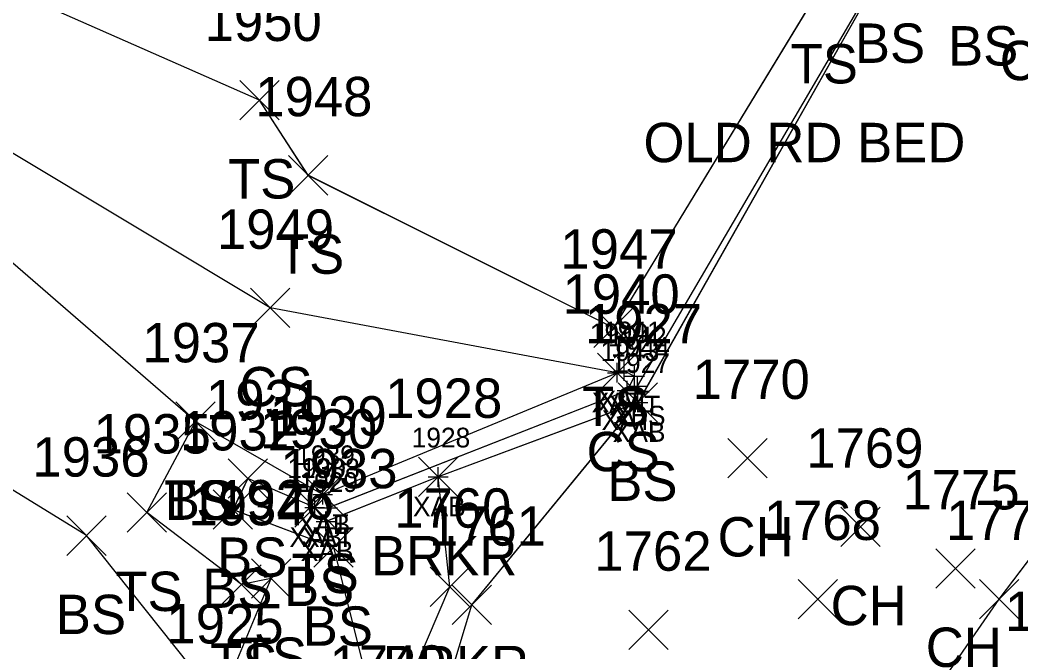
# Model space of a CAD drawing. Extents: x 1415642 to 1422021, y 544543 to 547232.
# Drawn here: x 1416156.1 to 1416207, y 546868.3 to 546900.4 of the extents above; entities that cross this region are included whole.
import ezdxf

# ---------------------------------------------------------------- set-up
doc = ezdxf.new("R2010")
doc.units = 0
for name, color, linetype in [('B_A', 7, 'Continuous'), ('B_I', 7, 'Continuous'), ('B_TIC', 7, 'Continuous'), ('BSE', 7, 'Continuous'), ('BSUBM', 7, 'Continuous'), ('L_A', 7, 'Continuous'), ('L_C', 7, 'Continuous'), ('L_I', 7, 'Continuous'), ('L_TIC', 7, 'Continuous'), ('LAWE', 7, 'Continuous'), ('LELB', 7, 'Continuous')]:
    doc.layers.add(name, color=color, linetype=linetype)

msp = doc.modelspace()

# ---------------------------------------------------------------- linework, layer by layer
at = {"layer": 'B_TIC'}
for p, q in [((1416186.471, 546882.455), (1416186.546, 546882.455)), ((1416186.817, 546882.554), (1416186.892, 546882.554)), ((1416187.348, 546882.292), (1416187.423, 546882.292)), ((1416186.972, 546881.556), (1416187.048, 546881.556)), ((1416186.972, 546881.556), (1416187.048, 546881.556)), ((1416187.506, 546881.78), (1416187.581, 546881.78)), ((1416187.522, 546880.949), (1416187.598, 546880.949)), ((1416177.376, 546877.166), (1416177.451, 546877.166)), ((1416171.517, 546876.268), (1416171.592, 546876.268)), ((1416171.517, 546876.268), (1416171.592, 546876.268)), ((1416171.104, 546875.611), (1416171.18, 546875.611)), ((1416171.763, 546875.605), (1416171.839, 546875.605)), ((1416171.763, 546875.605), (1416171.839, 546875.605)), ((1416171.677, 546874.904), (1416171.752, 546874.904))]:
    msp.add_line(p, q, dxfattribs=at)
for points in [[(1416186.467, 546881.955), (1416186.467, 546882.955)], [(1416186.813, 546882.054), (1416186.813, 546883.054)], [(1416185.967, 546882.455), (1416186.967, 546882.455)], [(1416186.313, 546882.554), (1416187.313, 546882.554)], [(1416187.344, 546881.792), (1416187.344, 546882.792)], [(1416186.844, 546882.292), (1416187.844, 546882.292)], [(1416186.969, 546881.056), (1416186.969, 546882.056)], [(1416186.969, 546881.056), (1416186.969, 546882.056)], [(1416187.502, 546881.28), (1416187.502, 546882.28)], [(1416186.469, 546881.556), (1416187.469, 546881.556)], [(1416186.469, 546881.556), (1416187.469, 546881.556)], [(1416187.002, 546881.78), (1416188.002, 546881.78)], [(1416187.519, 546880.449), (1416187.519, 546881.449)], [(1416187.019, 546880.949), (1416188.019, 546880.949)], [(1416177.372, 546876.666), (1416177.372, 546877.666)], [(1416171.514, 546875.768), (1416171.514, 546876.768)], [(1416171.514, 546875.768), (1416171.514, 546876.768)], [(1416176.872, 546877.166), (1416177.872, 546877.166)], [(1416171.014, 546876.268), (1416172.014, 546876.268)], [(1416171.014, 546876.268), (1416172.014, 546876.268)], [(1416171.101, 546875.111), (1416171.101, 546876.111)], [(1416171.76, 546875.105), (1416171.76, 546876.105)], [(1416171.76, 546875.105), (1416171.76, 546876.105)], [(1416170.601, 546875.611), (1416171.601, 546875.611)], [(1416171.26, 546875.605), (1416172.26, 546875.605)], [(1416171.26, 546875.605), (1416172.26, 546875.605)], [(1416171.674, 546874.404), (1416171.674, 546875.404)], [(1416171.173, 546874.904), (1416172.174, 546874.904)]]:
    msp.add_lwpolyline(points, dxfattribs=at)
at = {"layer": 'BSE'}
for points in [[(1416187.499, 546881.779), (1416199.573, 546902.416)], [(1416187.502, 546881.78), (1416199.572, 546902.416)]]:
    msp.add_lwpolyline(points, dxfattribs=at)
at = {"layer": 'BSUBM'}
for points in [[(1416198.776, 546903.573), (1416195.114, 546917.162), (1416197.142, 546917.846), (1416200.051, 546905.663), (1416200.095, 546903.197), (1416187.519, 546880.949), (1416177.372, 546877.166), (1416171.674, 546874.904), (1416171.101, 546875.611), (1416171.514, 546876.268)], [(1416198.778, 546903.573), (1416195.119, 546917.164), (1416197.143, 546917.845), (1416200.053, 546905.663), (1416200.097, 546903.197), (1416187.522, 546880.948), (1416177.378, 546877.165), (1416171.676, 546874.903), (1416171.104, 546875.611), (1416171.516, 546876.267)], [(1416171.76, 546875.605), (1416171.514, 546876.268), (1416186.467, 546882.455), (1416186.813, 546882.554), (1416187.344, 546882.292), (1416186.969, 546881.556)], [(1416171.765, 546875.604), (1416171.516, 546876.267), (1416186.466, 546882.454), (1416186.811, 546882.554), (1416187.343, 546882.291), (1416186.972, 546881.556)], [(1416171.76, 546875.605), (1416186.969, 546881.556)], [(1416171.765, 546875.604), (1416186.972, 546881.556)]]:
    msp.add_lwpolyline(points, dxfattribs=at)
at = {"layer": 'L_TIC'}
for points in [[(1416167.292, 546895.307), (1416169.292, 546897.307)], [(1416169.292, 546895.307), (1416167.292, 546897.307)], [(1416169.776, 546891.486), (1416171.776, 546893.486)], [(1416171.776, 546891.486), (1416169.776, 546893.486)], [(1416167.837, 546884.751), (1416169.837, 546886.751)], [(1416169.837, 546884.751), (1416167.837, 546886.751)], [(1416185.273, 546883.747), (1416187.273, 546885.747)], [(1416187.273, 546883.747), (1416185.273, 546885.747)], [(1416185.467, 546881.455), (1416187.467, 546883.455)], [(1416187.467, 546881.455), (1416185.467, 546883.455)], [(1416186.519, 546879.949), (1416188.519, 546881.949)], [(1416188.519, 546879.949), (1416186.519, 546881.949)], [(1416164.046, 546878.987), (1416166.046, 546880.987)], [(1416166.046, 546878.987), (1416164.046, 546880.987)], [(1416164.046, 546878.987), (1416166.046, 546880.987)], [(1416166.046, 546878.987), (1416164.046, 546880.987)], [(1416192.076, 546877.126), (1416194.076, 546879.126)], [(1416194.076, 546877.126), (1416192.076, 546879.126)], [(1416166.707, 546876.092), (1416168.707, 546878.092)], [(1416168.707, 546876.092), (1416166.707, 546878.092)], [(1416176.372, 546876.166), (1416178.372, 546878.166)], [(1416178.372, 546876.166), (1416176.372, 546878.166)], [(1416170.514, 546875.268), (1416172.514, 546877.268)], [(1416172.514, 546875.268), (1416170.514, 546877.268)], [(1416161.57, 546874.357), (1416163.57, 546876.357)], [(1416163.57, 546874.357), (1416161.57, 546876.357)], [(1416165.949, 546874.515), (1416167.949, 546876.515)], [(1416167.949, 546874.515), (1416165.949, 546876.515)], [(1416170.101, 546874.611), (1416172.101, 546876.611)], [(1416172.101, 546874.611), (1416170.101, 546876.611)], [(1416197.814, 546873.636), (1416199.814, 546875.636)], [(1416199.814, 546873.636), (1416197.814, 546875.636)], [(1416158.514, 546873.184), (1416160.514, 546875.184)], [(1416160.514, 546873.184), (1416158.514, 546875.184)], [(1416171.052, 546872.591), (1416173.052, 546874.591)], [(1416173.052, 546872.591), (1416171.052, 546874.591)], [(1416202.646, 546871.516), (1416204.646, 546873.516)], [(1416204.646, 546871.516), (1416202.646, 546873.516)], [(1416166.385, 546870.708), (1416168.385, 546872.708)], [(1416168.385, 546870.708), (1416166.385, 546872.708)], [(1416167.887, 546871.01), (1416169.887, 546873.01)], [(1416169.887, 546871.01), (1416167.887, 546873.01)], [(1416176.966, 546870.587), (1416178.966, 546872.587)], [(1416178.966, 546870.587), (1416176.966, 546872.587)], [(1416178.075, 546869.677), (1416180.075, 546871.677)], [(1416180.075, 546869.677), (1416178.075, 546871.677)], [(1416195.648, 546869.964), (1416197.648, 546871.964)], [(1416197.648, 546869.964), (1416195.648, 546871.964)], [(1416204.86, 546869.962), (1416206.86, 546871.962)], [(1416206.86, 546869.962), (1416204.86, 546871.962)], [(1416187.048, 546868.4), (1416189.048, 546870.4)], [(1416189.048, 546868.4), (1416187.048, 546870.4)]]:
    msp.add_lwpolyline(points, dxfattribs=at)
at = {"layer": 'LAWE'}
for points in [[(1416180.264, 546848.229), (1416177.092, 546851.48), (1416173.654, 546854.727), (1416174.556, 546863.614), (1416177.966, 546871.587), (1416177.372, 546877.166)], [(1416180.263, 546848.23), (1416177.089, 546851.481), (1416173.655, 546854.727), (1416174.555, 546863.614), (1416177.972, 546871.586), (1416177.378, 546877.165)]]:
    msp.add_lwpolyline(points, dxfattribs=at)
at = {"layer": 'LELB'}
for points in [[(1416166.265, 546865.71), (1416159.514, 546874.184), (1416128.857, 546893.051), (1416099.942, 546911.946), (1416080.109, 546927.167), (1416051.607, 546951.273), (1416024.788, 546978.542), (1415989.847, 547005.498), (1415949.916, 547022.61), (1415918.775, 547047.798), (1415880.242, 547071.016), (1415848.802, 547092.398)], [(1416166.265, 546865.71), (1416159.513, 546874.184), (1416128.861, 546893.052), (1416099.946, 546911.942), (1416080.11, 546927.168), (1416051.609, 546951.273), (1416024.792, 546978.539), (1415989.849, 547005.496), (1415949.921, 547022.607), (1415918.779, 547047.795), (1415880.245, 547071.014), (1415848.804, 547092.397)], [(1416196.863, 546902.153), (1416186.273, 546884.747), (1416170.776, 546892.486), (1416168.292, 546896.307), (1416136.943, 546910.117), (1416109.316, 546929.338), (1416090.972, 546938.603), (1416053.507, 546955.398), (1416024.788, 546978.542)], [(1416196.86, 546902.152), (1416186.278, 546884.748), (1416170.777, 546892.485), (1416168.295, 546896.308), (1416136.941, 546910.113), (1416109.318, 546929.334), (1416090.974, 546938.599), (1416053.511, 546955.394), (1416024.792, 546978.539)], [(1416165.046, 546879.987), (1416134.798, 546906.212), (1416107.439, 546926.284), (1416090.972, 546938.603)], [(1416165.05, 546879.986), (1416134.799, 546906.211), (1416107.441, 546926.281), (1416090.974, 546938.599)], [(1416186.467, 546882.455), (1416168.837, 546885.751), (1416134.798, 546906.212)], [(1416186.466, 546882.454), (1416168.841, 546885.751), (1416134.799, 546906.211)], [(1416176.093, 546860.732), (1416180.087, 546857.049), (1416183.159, 546854.485), (1416187.271, 546856.147), (1416195.123, 546858.506), (1416198.641, 546860.512), (1416205.866, 546870.961), (1416221.045, 546890.959)], [(1416176.093, 546860.732), (1416180.082, 546857.051), (1416183.156, 546854.486), (1416187.271, 546856.147), (1416195.126, 546858.505), (1416198.642, 546860.512), (1416205.86, 546870.962), (1416221.039, 546890.958)], [(1416176.093, 546860.732), (1416179.075, 546870.677), (1416187.519, 546880.949)], [(1416176.093, 546860.732), (1416179.074, 546870.677), (1416187.522, 546880.948)], [(1416225.048, 546830.585), (1416212.797, 546833.843), (1416194.801, 546838.18), (1416194.662, 546841.719), (1416184.984, 546843.165), (1416179.483, 546844.903), (1416167.887, 546851.572), (1416170.548, 546858.498), (1416166.265, 546865.71), (1416168.887, 546872.01), (1416167.385, 546871.708), (1416162.57, 546875.357), (1416165.046, 546879.987), (1416171.514, 546876.268)], [(1416225.049, 546830.584), (1416212.797, 546833.845), (1416194.799, 546838.183), (1416194.662, 546841.718), (1416184.984, 546843.165), (1416179.486, 546844.901), (1416167.885, 546851.573), (1416170.55, 546858.497), (1416166.265, 546865.71), (1416168.891, 546872.009), (1416167.387, 546871.708), (1416162.572, 546875.356), (1416165.05, 546879.986), (1416171.516, 546876.267)], [(1416171.101, 546875.611), (1416167.707, 546877.092), (1416166.949, 546875.515), (1416172.052, 546873.591)], [(1416171.104, 546875.611), (1416167.712, 546877.092), (1416166.953, 546875.515), (1416172.057, 546873.591)], [(1416172.052, 546873.591), (1416174.556, 546863.614)], [(1416172.057, 546873.591), (1416174.555, 546863.614)]]:
    msp.add_lwpolyline(points, dxfattribs=at)

# ---------------------------------------------------------------- texts
at = {"layer": 'B_A'}
for s, p in [('XAT', (1416185.172, 546880.455)), ('XAT', (1416185.518, 546880.554)), ('XAT', (1416186.049, 546880.292)), ('XAT', (1416185.674, 546879.556)), ('XAT', (1416185.674, 546879.556)), ('XBS', (1416186.242, 546879.78)), ('XAB', (1416186.239, 546878.949)), ('XAB', (1416176.093, 546875.166)), ('XAT', (1416170.218, 546874.268)), ('XAB', (1416170.234, 546874.268)), ('XAB', (1416169.821, 546873.611)), ('XAT', (1416170.464, 546873.605)), ('XAT', (1416170.464, 546873.605)), ('XAB', (1416170.394, 546872.904))]:
    msp.add_text(s, height=1, dxfattribs=at).set_placement(p)
at = {"layer": 'B_I'}
for s, p in [('1940', (1416185.077, 546883.955)), ('1941', (1416185.75, 546884.054)), ('1942', (1416185.998, 546883.792)), ('1943', (1416185.623, 546883.056)), ('1943', (1416185.623, 546883.056)), ('1944', (1416186.156, 546883.28)), ('1927', (1416186.172, 546882.449)), ('1928', (1416176.026, 546878.666)), ('1939', (1416170.163, 546877.768)), ('1939', (1416170.163, 546877.768)), ('1930', (1416169.711, 546877.111)), ('1938', (1416170.413, 546877.105)), ('1938', (1416170.413, 546877.105)), ('1929', (1416170.323, 546876.404))]:
    msp.add_text(s, height=1, dxfattribs=at).set_placement(p)
at = {"layer": 'L_A'}
for s, p in [('BS', (1416198.535, 546898.197)), ('BS', (1416203.268, 546898.063)), ('TS', (1416195.272, 546897.153)), ('TS', (1416195.272, 546897.153)), ('CH', (1416205.89, 546897.319)), ('TS', (1416166.701, 546891.307)), ('TS', (1416169.185, 546887.486)), ('CS', (1416167.278, 546880.751)), ('TS', (1416184.682, 546879.747)), ('CS', (1416184.908, 546877.455)), ('BS', (1416185.959, 546875.949)), ('TS', (1416163.455, 546874.987)), ('BS', (1416163.487, 546874.987)), ('CH', (1416191.564, 546873.126)), ('BS', (1416166.148, 546872.092)), ('BRKR', (1416173.963, 546872.166)), ('TS', (1416169.923, 546871.268)), ('TS', (1416160.979, 546870.357)), ('BS', (1416165.39, 546870.515)), ('BS', (1416169.542, 546870.611)), ('CH', (1416197.303, 546869.636)), ('BS', (1416157.955, 546869.184)), ('BS', (1416170.493, 546868.591)), ('CH', (1416202.134, 546867.516)), ('TS', (1416165.795, 546866.708)), ('TS', (1416167.297, 546867.01)), ('BRKR', (1416174.557, 546866.587))]:
    msp.add_text(s, height=2, dxfattribs=at).set_placement(p)
at = {"layer": 'L_C'}
msp.add_text('OLD RD BED', height=2, dxfattribs=at).set_placement((1416187.8, 546893.153))
msp.add_text('OLD RD BED', height=2, dxfattribs=at).set_placement((1416187.8, 546893.153))
at = {"layer": 'L_I'}
for s, p in [('1950', (1416165.512, 546899.307)), ('1948', (1416168.083, 546895.486)), ('1949', (1416166.136, 546888.751)), ('1947', (1416183.58, 546887.747)), ('1940', (1416183.688, 546885.455)), ('1927', (1416184.826, 546883.949)), ('1937', (1416162.353, 546882.987)), ('1937', (1416162.353, 546882.987)), ('1770', (1416190.296, 546881.126)), ('1931', (1416165.581, 546880.092)), ('1928', (1416174.679, 546880.166)), ('1939', (1416168.813, 546879.268)), ('1935', (1416159.877, 546878.357)), ('1932', (1416164.256, 546878.515)), ('1930', (1416168.321, 546878.611)), ('1769', (1416196.066, 546877.636)), ('1936', (1416156.766, 546877.184)), ('1933', (1416169.359, 546876.591)), ('1775', (1416200.953, 546875.516)), ('1926', (1416166.139, 546875.01)), ('1934', (1416164.692, 546874.708)), ('1760', (1416175.139, 546874.587)), ('1768', (1416193.908, 546873.964)), ('1774', (1416203.168, 546873.962)), ('1761', (1416176.901, 546873.677)), ('1762', (1416185.308, 546872.4)), ('1772', (1416206.159, 546869.343)), ('1925', (1416163.572, 546868.71)), ('1925', (1416163.572, 546868.71)), ('1749', (1416171.855, 546866.614))]:
    msp.add_text(s, height=2, dxfattribs=at).set_placement(p)

doc.saveas('drawing.dxf')
